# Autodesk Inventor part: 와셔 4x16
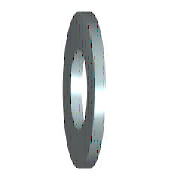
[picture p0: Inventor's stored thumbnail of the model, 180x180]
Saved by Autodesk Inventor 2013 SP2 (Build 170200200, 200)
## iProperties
IsCustomPart: 1
Created: 2012-02
Part Number: 와셔 4x16
Material: 강철, 연강
Description: 미터법 평면 와셔
Document SubType Name: Modeling
Standard: ANSI B18.22M
Designer: mduedu
Standard Revision: 1999
Standards Organization: ANSI
Language: ko-KR
Size Designation: 4 W
Categories: <MemberInstance><Categories><Category DisplayName="조임쇠" InternalName="e4da775c-781d-43d5-af7c-5136215cf5a6" Mnemonic="FSTN"><Category DisplayName="와셔" InternalN
Density: 1 g/cm^3
Author: mduedu
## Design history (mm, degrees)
sketch "스케치"
  geometry: C1 r 8 at (0, 0); C2 r 2.35 at (0, 0); 1 further point
  constraints: 2 centre point, 2 coincident
  dimensions: "d0" = 4.7 diameter of C2 (= SD1); "d1" = 16 diameter of C1 (= SD2)
extrude "본체" new body sketch "스케치" distance "d2" = 2.3 (= SD); taper "d3" = 0 deg
workaxis "Work Axis1"
workplane "Work Plane1"
body "Solid1"
other parameters: "SD1" = 4.7 [user parameter; used in 1 equation term], "SD2" = 16 [user parameter; used in 1 equation term], "SD" = 2.3 [user parameter; used in 1 equation term], "d4" = 0, "d5" = 0, "d6" = 0, "d7" = 0, "NND" = 4 [user parameter]
